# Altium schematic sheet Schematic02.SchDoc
size A; SheetNumber: 1; SheetTotal: 1
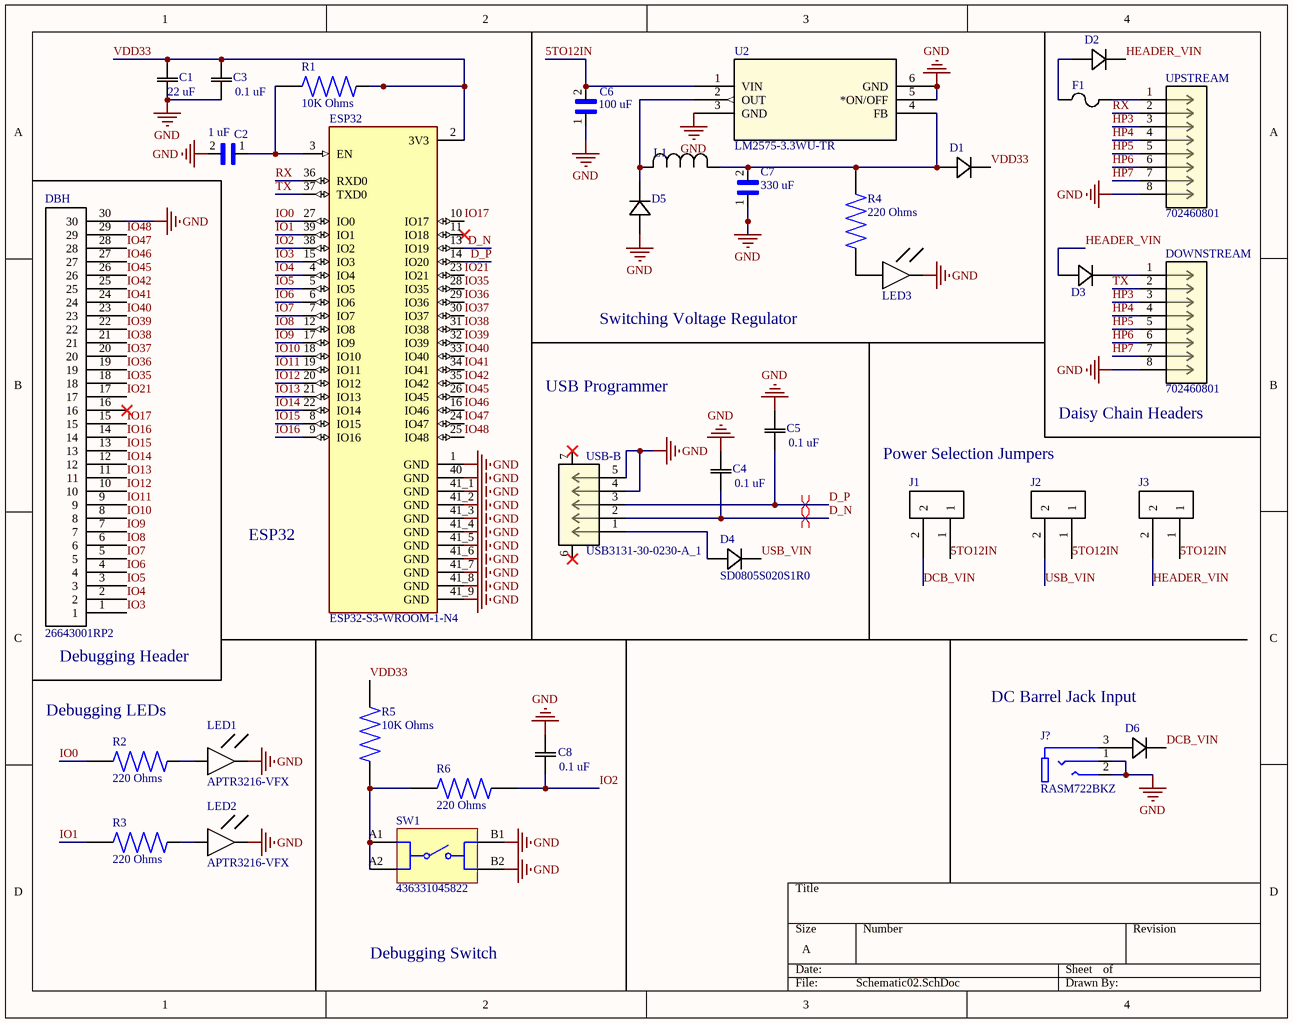
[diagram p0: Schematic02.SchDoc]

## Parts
C1  value 22 uF  [CAP_CL_21_SAM]  (hidden comment: CL21A226MAYNNNE)
C2  value 1 uF  [CAPC2012X140N]  (hidden comment: CL21B105KBFNNNE)
C3  value 0.1 uF  [CAPC2012X06N]  (hidden comment: THISONE08053C104KAT2A)
C4  value 0.1 uF  [CAPC2012X06N]  (hidden comment: THISONE08053C104KAT2A)
C5  value 0.1 uF  [CAPC2012X06N]  (hidden comment: THISONE08053C104KAT2A)
C6  value 100 uF  [CAPC3216X190N]  (hidden comment: GRM31CR61A107MEA8L)
C7  value 330 uF  [CAPC3225X280N]  (hidden comment: JMK325ABJ337MM-PE)
C8  value 0.1 uF  [CAPC2012X06N]  (hidden comment: THISONE08053C104KAT2A)
D1  SD0805S020S1R0  [SD0805_AVX]  (value not drawn)
D2  SD0805S020S1R0  [SD0805_AVX]  (value not drawn)
D3  SD0805S020S1R0  [SD0805_AVX]  (value not drawn)
D4  SD0805S020S1R0  [SD0805_AVX]
D5  SD0805S020S1R0  [SD0805_AVX]  (value not drawn)
D6  SD0805S020S1R0  [SD0805_AVX]  (value not drawn)
DBH  26643001RP2  [26643001RP2-Footprint-1]
DOWNSTREAM  702460801  [CONN_7024608xx_MOL]
ESP32  ESP32-S3-WROOM-1-N4  [XCVR_ESP32-S3-WROOM-1-N4]
F1  0154.630DR  [0154Series_LTF]  (value not drawn)
J1  2x1JUMPER  [26640201RP2-Footprint-1]  (value not drawn)
J2  2x1JUMPER  [26640201RP2-Footprint-1]  (value not drawn)
J3  2x1JUMPER  [26640201RP2-Footprint-1]  (value not drawn)
J?  RASM722BKZ  [SWITCHCRAFT_RASM722BKZ]
L1  NR10050T221M  [INDP10198X50N]  (value not drawn)
LED1  APTR3216-VFX  [SODFL350X110-2N]
LED2  APTR3216-VFX  [SODFL350X110-2N]
LED3  APTR3216-VFX  [SODFL350X110-2N]  (value not drawn)
R1  10K Ohms  [RESC3116X65N]
R2  220 Ohms  [RESC2012X65N]
R3  220 Ohms  [RESC2012X65N]
R4  220 Ohms  [RESC2012X65N]
R5  10K Ohms  [RESC3116X65N]
R6  220 Ohms  [RESC2012X65N]
SW1  436331045822  [436331045822]
U2  LM2575-3.3WU-TR  [DPAK183P1580X460-6N]
UPSTREAM  702460801  [CONN_7024608xx_MOL]
USB-B  USB3131-30-0230-A_1  [USB3131-30-0230-A_1-Footprint-1]

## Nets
GND: C1.1 C2.2 C3.1 C4.2 C5.2 C6.1 C7.1 C8.1 D5.2 DBH.30 DOWNSTREAM.8 ESP32.1(GND) ESP32.40(GND) ESP32.41_1(GND) ESP32.41_2(GND) ESP32.41_3(GND) ESP32.41_4(GND) ESP32.41_5(GND) ESP32.41_6(GND) ESP32.41_7(GND) ESP32.41_8(GND) ESP32.41_9(GND) J?.1(SHUNT) J?.2(TIP) LED1.1 LED2.1 LED3.1 SW1.B1 SW1.B2 U2.3(GND) U2.5(*ON/OFF) U2.6(GND) UPSTREAM.8 USB-B.4 USB-B.5
5TO12IN: C6.2 J1.1 J2.1 J3.1 U2.1(VIN)
D_N: C4.1 ESP32.13(IO19) USB-B.2
D_P: C5.1 ESP32.14(IO20) USB-B.3
DCB_VIN: D6.1 J1.2
HEADER_VIN: D2.1 D3.2 J3.2
HP3: DOWNSTREAM.3 UPSTREAM.3
HP4: DOWNSTREAM.4 UPSTREAM.4
HP5: DOWNSTREAM.5 UPSTREAM.5
HP6: DOWNSTREAM.6 UPSTREAM.6
HP7: DOWNSTREAM.7 UPSTREAM.7
IO0: ESP32.27(IO0) R2.1
IO1: ESP32.39(IO1) R3.1
IO2: C8.2 ESP32.38(IO2) R6.2
IO3: DBH.1 ESP32.15(IO3)
IO4: DBH.2 ESP32.4(IO4)
IO5: DBH.3 ESP32.5(IO5)
IO6: DBH.4 ESP32.6(IO6)
IO7: DBH.5 ESP32.7(IO7)
IO8: DBH.6 ESP32.12(IO8)
IO9: DBH.7 ESP32.17(IO9)
IO10: DBH.8 ESP32.18(IO10)
IO11: DBH.9 ESP32.19(IO11)
IO12: DBH.10 ESP32.20(IO12)
IO13: DBH.11 ESP32.21(IO13)
IO14: DBH.12 ESP32.22(IO14)
IO15: DBH.13 ESP32.8(IO15)
IO16: DBH.14 ESP32.9(IO16)
IO17: DBH.15 ESP32.10(IO17)
IO21: DBH.17 ESP32.23(IO21)
IO35: DBH.18 ESP32.28(IO35)
IO36: DBH.19 ESP32.29(IO36)
IO37: DBH.20 ESP32.30(IO37)
IO38: DBH.21 ESP32.31(IO38)
IO39: DBH.22 ESP32.32(IO39)
IO40: DBH.23 ESP32.33(IO40)
IO41: DBH.24 ESP32.34(IO41)
IO42: DBH.25 ESP32.35(IO42)
IO45: DBH.26 ESP32.26(IO45)
IO46: DBH.27 ESP32.16(IO46)
IO47: DBH.28 ESP32.24(IO47)
IO48: DBH.29 ESP32.25(IO48)
RX: ESP32.36(RXD0) UPSTREAM.2
TX: DOWNSTREAM.2 ESP32.37(TXD0)
USB_VIN: D4.1 J2.2
VDD33: C1.2 C3.2 D1.1 ESP32.2(3V3) R1.2 R5.2
NetC2_1: C2.1 ESP32.3(EN) R1.1
NetC7_2: C7.2 D1.2 L1.1 R4.2 U2.4(FB)
NetD2_2: D2.2 F1.1
NetD3_1: D3.1 DOWNSTREAM.1
NetD4_2: D4.2 USB-B.1
NetD5_1: D5.1 L1.2 U2.2(OUT)
NetD6_2: D6.2 J?.3(SLEEVE)
NetF1_2: F1.2 UPSTREAM.1
NetLED1_2: LED1.2 R2.2
NetLED2_2: LED2.2 R3.2
NetLED3_2: LED3.2 R4.1
NetR5_1: R5.1 R6.1 SW1.A1 SW1.A2

Not connected (* = marked no-connect by the designer): DBH 16*; ESP32 11(IO18)*; USB-B 6* 7*

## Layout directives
differential pair: D_N, D_P

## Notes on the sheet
- Switching Voltage Regulator
- USB Programmer
- (near DOWNSTREAM) Daisy Chain Headers
- Power Selection Jumpers
- (near ESP32) ESP32
- (near DBH) Debugging Header
- DC Barrel Jack Input
- Debugging LEDs
- Debugging Switch

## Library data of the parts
C1 = CMP-017-000005-2: No Description Available; Mfr_Name: Samsung
C2 = CMP-017-000007-1: 1ÂµF Â±10% 50V Ceramic Capacitor X7R 0805 _2012 Metric_; MF: Samsung
C3-C5 C8 = CMP-017-000003-3: No Description Available; Mfr_Name: KYOCERA AVX
C6 = CMP-017-000006-1
C7 = CMP-017-000008-1: 330ÂµF Â±20% 6.3V Ceramic Capacitor X5R 1210 (3225 Metric); MF: Taiyo Yuden
D1-D6 = CMP-024-000001-3: No Description Available; Mfr_Name: KYOCERA AVX
DBH = CMP-00006-3: Board Connector
DOWNSTREAM UPSTREAM = CMP-004-000000-1: No Description Available; Mfr_Name: Molex Connector Corporation
ESP32 = CMP-006-000000-1: MF: {'manufacturer': u'Espressif Systems'}
F1 = CMP-010-000000-2: No Description Available; Mfr_Name: Littelfuse Inc
J1-J3 = CMP-00005-3: Board Connector
J? = CMP-020-000000-1: MF: Switchcraft Inc.
L1 = CMP-028-000000-2: No Description Available; Mfr_Name: Taiyo Yuden
LED1-LED3 = CMP-00009-1: violet LED
R1 R5 = CMP-017-000000-1: 10 kOhms Â±1% 0.25W, 1/4W Chip Resistor 1206 (3216 Metric) Moisture Resistant Thick Film; MF: Yageo
R2-R4 R6 = CMP-017-000002-1: Fixed Resistor CRGCQ 0805 220R 1%; MF: TE Connectivity
SW1 = CMP-015-000006-1: WS-TASU SMT Tact Switch with Boss Design 4.7x3.5mm side push, SPST-NO, 12VDC, 50mA, 220g; Manufacturer: Wurth Elektronik; Washable: No
U2 = CMP-013-000001-2: No Description Available; Mfr_Name: Microchip
USB-B = CMP-008-000002-2: No Description Available; Mfr_Name: Global Connector Technology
